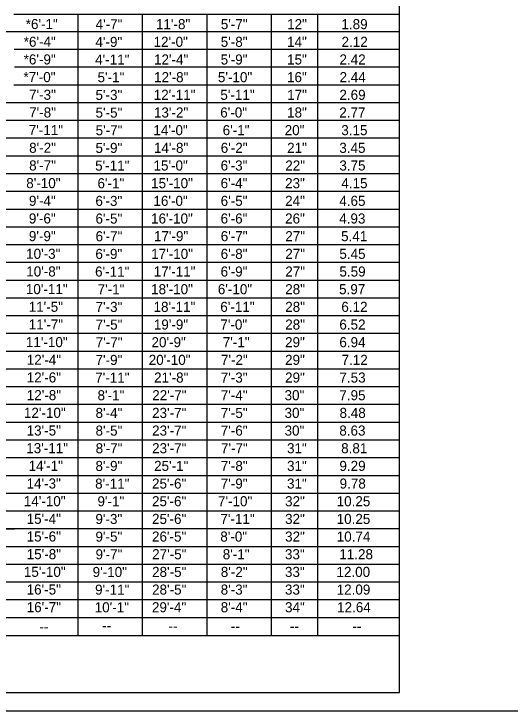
# Model space of a CAD drawing. Extents: x 1083.1 to 1117.1, y 675.4 to 741.4.
# Drawn here: x 1097.9 to 1105.58, y 719.85 to 730.66 of the extents above; entities that cross this region are included whole.
import ezdxf

# ---------------------------------------------------------------- set-up
doc = ezdxf.new("R2010")
doc.units = 0
doc.layers.add('Level 1', color=7, linetype='Continuous')

msp = doc.modelspace()

# ---------------------------------------------------------------- linework, layer by layer
at = {"layer": 'Level 1'}
for p, q in [((1103.868, 720.144), (1103.868, 734.976)), ((1097.894, 730.663), (1103.868, 730.663)), ((1098.89, 721.026), (1098.89, 730.663)), ((1099.889, 721.026), (1099.889, 730.663)), ((1100.889, 721.026), (1100.889, 730.663)), ((1101.889, 721.026), (1101.889, 730.663)), ((1102.605, 721.026), (1102.605, 730.663)), ((1103.868, 730.387), (1086.654, 730.387)), ((1103.868, 730.112), (1097.897, 730.112)), ((1103.868, 729.837), (1097.904, 729.837)), ((1103.868, 729.562), (1097.894, 729.562)), ((1103.868, 729.286), (1086.654, 729.286)), ((1103.868, 729.011), (1086.654, 729.011)), ((1103.868, 728.736), (1086.654, 728.736)), ((1103.868, 728.46), (1086.654, 728.46)), ((1103.868, 728.185), (1086.654, 728.185)), ((1103.868, 728.185), (1086.689, 728.185)), ((1103.868, 727.909), (1086.654, 727.909)), ((1103.868, 727.634), (1086.654, 727.634)), ((1103.868, 727.359), (1086.654, 727.359)), ((1103.868, 727.083), (1086.654, 727.083)), ((1103.868, 726.808), (1086.654, 726.808)), ((1103.868, 726.533), (1086.654, 726.533)), ((1103.868, 726.257), (1086.654, 726.257)), ((1103.868, 725.982), (1086.654, 725.982)), ((1103.868, 725.707), (1086.654, 725.707)), ((1103.868, 725.432), (1086.654, 725.432)), ((1103.868, 725.156), (1086.654, 725.156)), ((1103.868, 724.881), (1086.654, 724.881)), ((1103.868, 724.606), (1086.654, 724.606)), ((1103.868, 724.33), (1086.654, 724.33)), ((1103.868, 724.055), (1086.654, 724.055)), ((1103.868, 723.779), (1086.654, 723.779)), ((1103.868, 723.504), (1086.654, 723.504)), ((1103.868, 723.229), (1086.654, 723.229)), ((1103.868, 722.953), (1086.654, 722.953)), ((1097.909, 722.953), (1091.972, 722.953)), ((1103.868, 722.678), (1086.654, 722.678)), ((1091.98, 722.678), (1097.903, 722.678)), ((1103.868, 722.403), (1086.654, 722.403)), ((1103.868, 722.127), (1086.654, 722.127)), ((1103.868, 721.852), (1086.654, 721.852)), ((1103.868, 721.577), (1086.654, 721.577)), ((1103.868, 721.302), (1086.654, 721.302)), ((1086.654, 721.026), (1103.868, 721.026)), ((1086.654, 720.144), (1103.868, 720.144))]:
    msp.add_line(p, q, dxfattribs=at)
msp.add_lwpolyline([(1085.126, 740.854), (1116.626, 740.854), (1116.626, 719.854), (1085.126, 719.854)], close=True, dxfattribs=at)

# ---------------------------------------------------------------- texts
for s, height, p in [('*6\'-1"', 0.156, (1098.078, 730.429)), ('4\'-7"', 0.156, (1099.161, 730.427)), ('11\'-8"', 0.156, (1100.096, 730.428)), ('5\'-7"', 0.156, (1101.101, 730.428)), ('12"', 0.156, (1102.129, 730.428)), ('1.89', 0.156, (1102.97, 730.428)), ('*6\'-4"', 0.156, (1098.047, 730.155)), ('4\'-9"', 0.156, (1099.158, 730.153)), ('12\'-0"', 0.156, (1100.059, 730.154)), ('5\'-8"', 0.156, (1101.1, 730.154)), ('14"', 0.156, (1102.128, 730.154)), ('2.12', 0.156, (1102.972, 730.154)), ('*6\'-9"', 0.156, (1098.046, 729.881)), ('4\'-11"', 0.156, (1099.154, 729.879)), ('12\'-4"', 0.156, (1100.066, 729.88)), ('5\'-9"', 0.156, (1101.099, 729.88)), ('15"', 0.156, (1102.128, 729.88)), ('2.42', 0.156, (1102.94, 729.88)), ('*7\'-0"', 0.156, (1098.043, 729.607)), ('5\'-1"', 0.156, (1099.191, 729.605)), ('12\'-8"', 0.156, (1100.067, 729.606)), ('5\'-10"', 0.156, (1101.056, 729.606)), ('16"', 0.156, (1102.127, 729.606)), ('2.44', 0.156, (1102.941, 729.606)), ('7\'-3"', 0.156, (1098.13, 729.333)), ('5\'-3"', 0.156, (1099.159, 729.331)), ('12\'-11"', 0.156, (1100.061, 729.332)), ('5\'-11"', 0.156, (1101.094, 729.332)), ('17"', 0.156, (1102.129, 729.332)), ('2.69', 0.156, (1102.939, 729.332)), ('7\'-8"', 0.156, (1098.131, 729.059)), ('5\'-5"', 0.156, (1099.16, 729.057)), ('13\'-2"', 0.156, (1100.065, 729.058)), ('6\'-0"', 0.156, (1101.092, 729.058)), ('18"', 0.156, (1102.128, 729.058)), ('2.77', 0.156, (1102.937, 729.058)), ('7\'-11"', 0.156, (1098.125, 728.785)), ('5\'-7"', 0.156, (1099.161, 728.783)), ('14\'-0"', 0.156, (1100.057, 728.784)), ('6\'-1"', 0.156, (1101.13, 728.784)), ('20"', 0.156, (1102.091, 728.784)), ('3.15', 0.156, (1102.968, 728.784)), ('8\'-2"', 0.156, (1098.131, 728.511)), ('5\'-9"', 0.156, (1099.159, 728.509)), ('14\'-8"', 0.156, (1100.065, 728.51)), ('6\'-2"', 0.156, (1101.1, 728.51)), ('21"', 0.156, (1102.129, 728.51)), ('3.45', 0.156, (1102.937, 728.51)), ('8\'-7"', 0.156, (1098.131, 728.237)), ('5\'-11"', 0.156, (1099.154, 728.235)), ('15\'-0"', 0.156, (1100.058, 728.236)), ('6\'-3"', 0.156, (1101.098, 728.236)), ('22"', 0.156, (1102.1, 728.236)), ('3.75', 0.156, (1102.938, 728.236)), ('8\'-10"', 0.156, (1098.086, 727.963)), ('6\'-1"', 0.156, (1099.19, 727.961)), ('15\'-10"', 0.156, (1100.021, 727.962)), ('6\'-4"', 0.156, (1101.098, 727.962)), ('23"', 0.156, (1102.097, 727.962)), ('4.15', 0.156, (1102.969, 727.962)), ('9\'-4"', 0.156, (1098.128, 727.689)), ('6\'-3"', 0.156, (1099.158, 727.687)), ('16\'-0"', 0.156, (1100.057, 727.688)), ('6\'-5"', 0.156, (1101.099, 727.688)), ('24"', 0.156, (1102.098, 727.688)), ('4.65', 0.156, (1102.937, 727.688)), ('9\'-6"', 0.156, (1098.127, 727.415)), ('6\'-5"', 0.156, (1099.159, 727.413)), ('16\'-10"', 0.156, (1100.02, 727.414)), ('6\'-6"', 0.156, (1101.098, 727.414)), ('26"', 0.156, (1102.097, 727.414)), ('4.93', 0.156, (1102.936, 727.414)), ('9\'-9"', 0.156, (1098.127, 727.141)), ('6\'-7"', 0.156, (1099.16, 727.139)), ('17\'-9"', 0.156, (1100.065, 727.14)), ('6\'-7"', 0.156, (1101.1, 727.14)), ('27"', 0.156, (1102.1, 727.14)), ('5.41', 0.156, (1102.965, 727.14)), ('10\'-3"', 0.156, (1098.084, 726.867)), ('6\'-9"', 0.156, (1099.158, 726.865)), ('17\'-10"', 0.156, (1100.022, 726.866)), ('6\'-8"', 0.156, (1101.099, 726.866)), ('27"', 0.156, (1102.1, 726.866)), ('5.45', 0.156, (1102.938, 726.866)), ('10\'-8"', 0.156, (1098.086, 726.593)), ('6\'-11"', 0.156, (1099.153, 726.591)), ('17\'-11"', 0.156, (1100.061, 726.592)), ('6\'-9"', 0.156, (1101.098, 726.592)), ('27"', 0.156, (1102.1, 726.592)), ('5.59', 0.156, (1102.939, 726.592)), ('10\'-11"', 0.156, (1098.08, 726.319)), ('7\'-1"', 0.156, (1099.192, 726.317)), ('18\'-10"', 0.156, (1100.021, 726.318)), ('6\'-10"', 0.156, (1101.055, 726.318)), ('28"', 0.156, (1102.099, 726.318)), ('5.97', 0.156, (1102.934, 726.318)), ('11\'-5"', 0.156, (1098.124, 726.045)), ('7\'-3"', 0.156, (1099.16, 726.043)), ('18\'-11"', 0.156, (1100.059, 726.044)), ('6\'-11"', 0.156, (1101.093, 726.044)), ('28"', 0.156, (1102.099, 726.044)), ('6.12', 0.156, (1102.969, 726.044)), ('11\'-7"', 0.156, (1098.125, 725.771)), ('7\'-5"', 0.156, (1099.161, 725.769)), ('19\'-9"', 0.156, (1100.063, 725.77)), ('7\'-0"', 0.156, (1101.094, 725.77)), ('28"', 0.156, (1102.099, 725.77)), ('6.52', 0.156, (1102.938, 725.77)), ('11\'-10"', 0.156, (1098.08, 725.497)), ('7\'-7"', 0.156, (1099.163, 725.495)), ('20\'-9"', 0.156, (1100.027, 725.496)), ('7\'-1"', 0.156, (1101.132, 725.496)), ('29"', 0.156, (1102.097, 725.496)), ('6.94', 0.156, (1102.938, 725.496)), ('12\'-4"', 0.156, (1098.094, 725.223)), ('7\'-9"', 0.156, (1099.16, 725.221)), ('20\'-10"', 0.156, (1099.984, 725.222)), ('7\'-2"', 0.156, (1101.103, 725.222)), ('29"', 0.156, (1102.097, 725.222)), ('7.12', 0.156, (1102.972, 725.222)), ('12\'-6"', 0.156, (1098.093, 724.949)), ('7\'-11"', 0.156, (1099.155, 724.947)), ('21\'-8"', 0.156, (1100.067, 724.948)), ('7\'-3"', 0.156, (1101.1, 724.948)), ('29"', 0.156, (1102.097, 724.948)), ('7.53', 0.156, (1102.939, 724.948)), ('12\'-8"', 0.156, (1098.094, 724.675)), ('8\'-1"', 0.156, (1099.191, 724.673)), ('22\'-7"', 0.156, (1100.038, 724.674)), ('7\'-4"', 0.156, (1101.101, 724.674)), ('30"', 0.156, (1102.089, 724.674)), ('7.95', 0.156, (1102.938, 724.674)), ('12\'-10"', 0.156, (1098.05, 724.401)), ('8\'-4"', 0.156, (1099.16, 724.399)), ('23\'-7"', 0.156, (1100.036, 724.4)), ('7\'-5"', 0.156, (1101.101, 724.4)), ('30"', 0.156, (1102.089, 724.4)), ('8.48', 0.156, (1102.941, 724.4)), ('13\'-5"', 0.156, (1098.092, 724.127)), ('8\'-5"', 0.156, (1099.16, 724.125)), ('23\'-7"', 0.156, (1100.036, 724.126)), ('7\'-6"', 0.156, (1101.1, 724.126)), ('30"', 0.156, (1102.089, 724.126)), ('8.63', 0.156, (1102.937, 724.126)), ('13\'-11"', 0.156, (1098.086, 723.853)), ('8\'-7"', 0.156, (1099.161, 723.851)), ('23\'-7"', 0.156, (1100.036, 723.852)), ('7\'-7"', 0.156, (1101.103, 723.852)), ('31"', 0.156, (1102.127, 723.852)), ('8.81', 0.156, (1102.966, 723.852)), ('14\'-1"', 0.156, (1098.123, 723.579)), ('8\'-9"', 0.156, (1099.159, 723.577)), ('25\'-1"', 0.156, (1100.067, 723.578)), ('7\'-8"', 0.156, (1101.101, 723.578)), ('31"', 0.156, (1102.127, 723.578)), ('9.29', 0.156, (1102.939, 723.578)), ('14\'-3"', 0.156, (1098.091, 723.305)), ('8\'-11"', 0.156, (1099.154, 723.303)), ('25\'-6"', 0.156, (1100.035, 723.304)), ('7\'-9"', 0.156, (1101.1, 723.304)), ('31"', 0.156, (1102.127, 723.304)), ('9.78', 0.156, (1102.942, 723.304)), ('14\'-10"', 0.156, (1098.048, 723.031)), ('9\'-1"', 0.156, (1099.19, 723.029)), ('25\'-6"', 0.156, (1100.035, 723.03)), ('7\'-10"', 0.156, (1101.057, 723.03)), ('32"', 0.156, (1102.097, 723.03)), ('10.25', 0.156, (1102.896, 723.03)), ('15\'-4"', 0.156, (1098.092, 722.757)), ('9\'-3"', 0.156, (1099.158, 722.755)), ('25\'-6"', 0.156, (1100.035, 722.756)), ('7\'-11"', 0.156, (1101.095, 722.756)), ('32"', 0.156, (1102.097, 722.756)), ('10.25', 0.156, (1102.896, 722.756)), ('15\'-6"', 0.156, (1098.092, 722.483)), ('9\'-5"', 0.156, (1099.159, 722.481)), ('26\'-5"', 0.156, (1100.035, 722.482)), ('8\'-0"', 0.156, (1101.093, 722.482)), ('32"', 0.156, (1102.097, 722.482)), ('10.74', 0.156, (1102.897, 722.482)), ('15\'-8"', 0.156, (1098.093, 722.209)), ('9\'-7"', 0.156, (1099.16, 722.207)), ('27\'-5"', 0.156, (1100.037, 722.208)), ('8\'-1"', 0.156, (1101.131, 722.208)), ('33"', 0.156, (1102.095, 722.208)), ('11.28', 0.156, (1102.937, 722.208)), ('15\'-10"', 0.156, (1098.049, 721.935)), ('9\'-10"', 0.156, (1099.115, 721.933)), ('28\'-5"', 0.156, (1100.036, 721.934)), ('8\'-2"', 0.156, (1101.101, 721.934)), ('33"', 0.156, (1102.095, 721.934)), ('12.00', 0.156, (1102.893, 721.934)), ('16\'-5"', 0.156, (1098.092, 721.661)), ('9\'-11"', 0.156, (1099.153, 721.659)), ('28\'-5"', 0.156, (1100.036, 721.66)), ('8\'-3"', 0.156, (1101.099, 721.66)), ('33"', 0.156, (1102.095, 721.66)), ('12.09', 0.156, (1102.896, 721.66)), ('16\'-7"', 0.156, (1098.093, 721.387)), ('10\'-1"', 0.156, (1099.147, 721.385)), ('29\'-4"', 0.156, (1100.034, 721.386)), ('8\'-4"', 0.156, (1101.1, 721.386)), ('34"', 0.156, (1102.096, 721.386)), ('12.64', 0.156, (1102.903, 721.386)), ('--', 0.16, (1098.288, 721.082)), ('--', 0.16, (1099.262, 721.101)), ('--', 0.16, (1100.288, 721.092)), ('--', 0.16, (1101.255, 721.09)), ('--', 0.16, (1102.171, 721.09)), ('--', 0.16, (1103.138, 721.09))]:
    msp.add_text(s, height=height, dxfattribs=at).set_placement(p)

doc.saveas('drawing.dxf')
